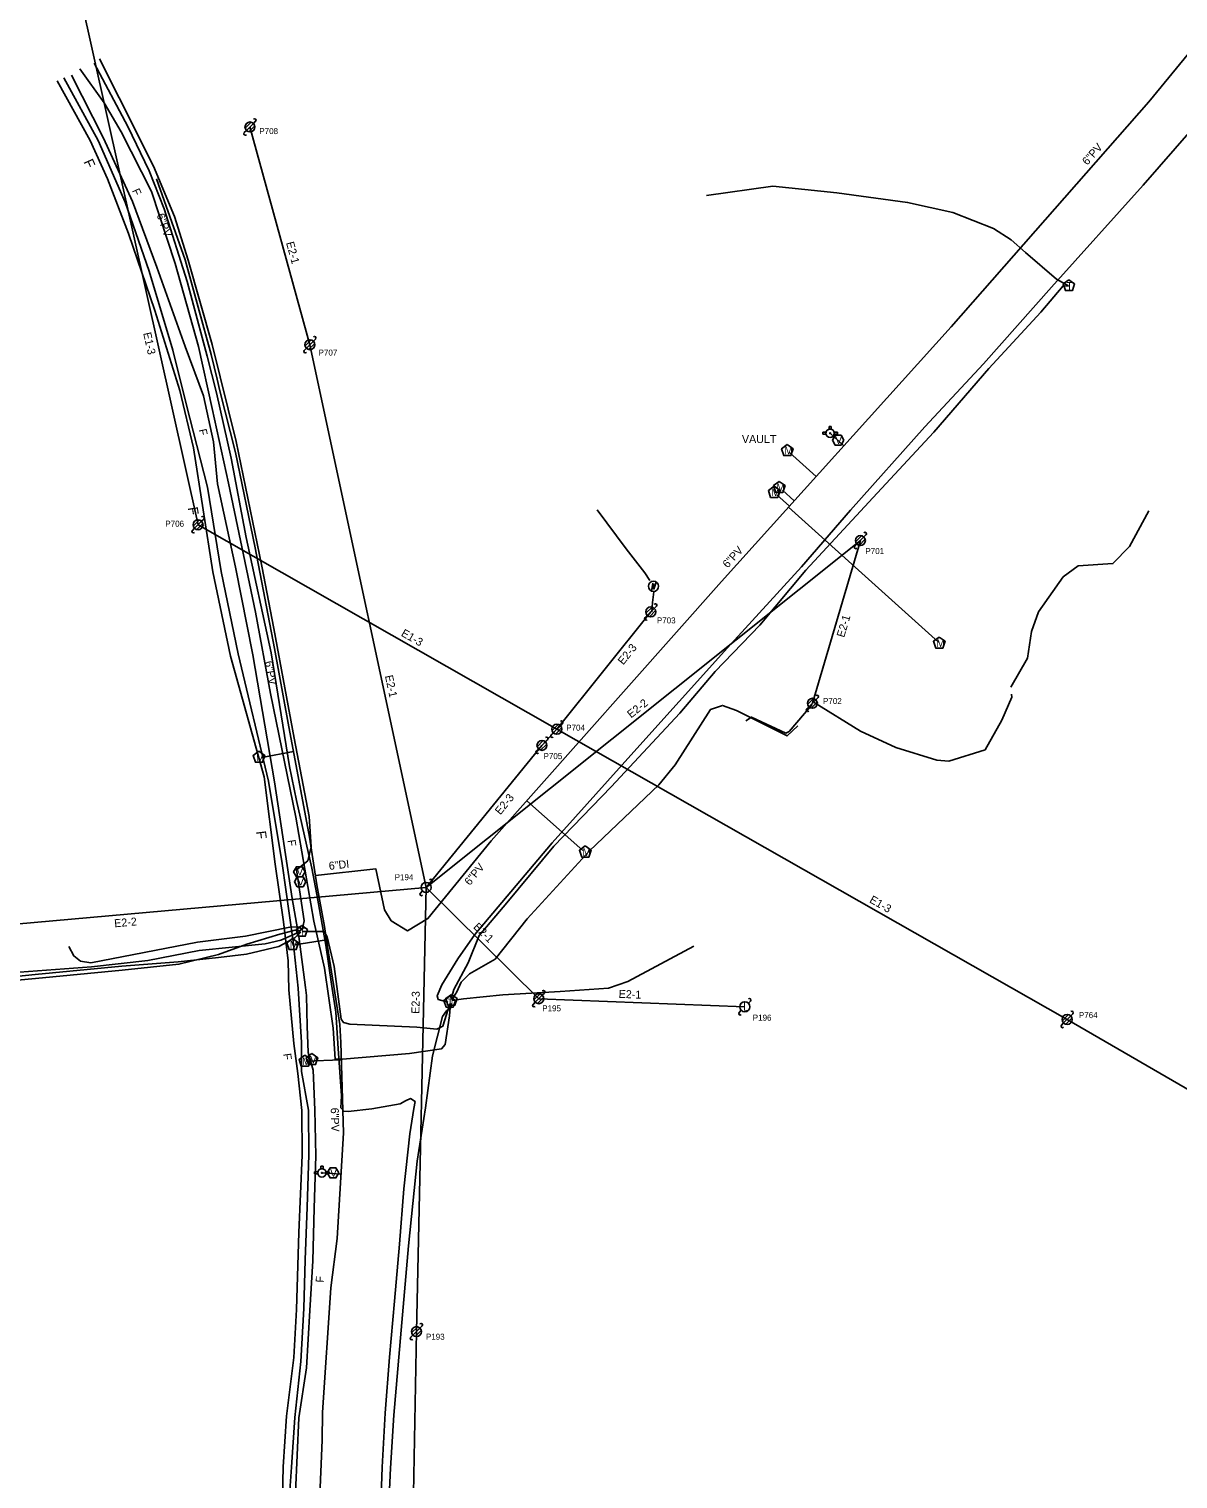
# Model space of a CAD drawing. Extents: x 1741604 to 1825760, y 1164229 to 1194908.
# Drawn here: x 1771883 to 1772457, y 1180447 to 1181171 of the extents above; entities that cross this region are included whole.
import ezdxf

# ---------------------------------------------------------------- set-up
doc = ezdxf.new("R2010")
doc.units = 0
for name, color, linetype in [('RD_EX_SU_Elec', 7, 'Continuous'), ('RD_EX_SU_H2O', 7, 'Continuous'), ('RD_EX_SU_Ovhd', 7, 'Continuous'), ('RD_EX_SU_Pole', 7, 'Continuous'), ('RD_EX_SU_Telecom', 7, 'Continuous'), ('RD_EX_SU_TX_H2O', 7, 'Continuous'), ('RD_EX_SU_TX_Pole', 7, 'Continuous'), ('RD_EX_SU_TX_Telecom', 7, 'Continuous')]:
    doc.layers.add(name, color=color, linetype=linetype)

# ---------------------------------------------------------------- blocks, each defined once
blk = doc.blocks.new('SUE_TPP')
at = {"layer": 'RD_EX_SU_Telecom'}
blk.add_lwpolyline([(0, 3), (-2.85, 0.93), (-1.76, -2.43), (1.76, -2.43), (2.85, 0.93)], close=True, dxfattribs=at)
blk.add_text('T', height=3.75, dxfattribs=at).set_placement((-1.25, -1.88))
blk = doc.blocks.new('SUE_PP')
at = {"layer": 'RD_EX_SU_Pole'}
for p, q in [((-2.41, -0.65), (0.65, 2.41)), ((-1.77, -1.77), (1.77, 1.77)), ((-0.65, -2.41), (2.41, 0.65)), ((1.77, 1.77), (2.83, 2.83)), ((-2.83, -2.83), (-1.77, -1.77))]:
    blk.add_line(p, q, dxfattribs=at)
blk.add_circle((0, 0), 2.5, dxfattribs=at)
for centre, start, end in [((2.3, 3.36), 315, 135), ((-2.3, -3.36), 135, 315)]:
    blk.add_arc(centre, 0.75, start, end, dxfattribs=at)
blk = doc.blocks.new('SUE_WV')
at = {"layer": 'RD_EX_SU_H2O'}
blk.add_lwpolyline([(2.89, 0), (1.44, 2.5), (-1.44, 2.5), (-2.89, 0), (-1.44, -2.5), (1.44, -2.5)], close=True, dxfattribs=at)
blk.add_text('V', height=3.75, dxfattribs=at).set_placement((-1.43, -1.88))
blk = doc.blocks.new('SUE_WFH')
at = {"layer": 'RD_EX_SU_H2O'}
for p, q in [((-2.01, 0.6), (-3.65, 0.6)), ((-3.65, 0.6), (-3.65, -0.45)), ((-0.48, 3.38), (-0.48, 2.04)), ((0.57, 3.38), (-0.48, 3.38)), ((0.57, 2.02), (0.57, 3.38)), ((3.7, 0.6), (2.01, 0.6)), ((3.7, -0.45), (3.7, 0.6)), ((-3.65, -0.45), (-2.05, -0.45)), ((2.05, -0.45), (3.7, -0.45))]:
    blk.add_line(p, q, dxfattribs=at)
for radius in [2.1, 0.263]:
    blk.add_circle((0, 0), radius, dxfattribs=at)
for start, end in [(163.3387, 192.31502), (74.24552, 103.21276), (347.68498, 16.6613)]:
    blk.add_arc((0, 0), 2.1, start, end, dxfattribs=at)
blk = doc.blocks.new('SUE_WM')
at = {"layer": 'RD_EX_SU_H2O'}
blk.add_lwpolyline([(0, 3.05), (-2.9, 0.94), (-1.79, -2.47), (1.79, -2.47), (2.9, 0.94)], close=True, dxfattribs=at)
blk.add_text('M', height=3.75, dxfattribs=at).set_placement((-1.43, -1.88))
blk = doc.blocks.new('SUE_ETM')
at = {"layer": 'RD_EX_SU_Elec'}
blk.add_lwpolyline([(1.24, 2.04), (0.23, -1.41), (-0.27, 0.46), (-1.03, -2.36), (-0.34, 1.55), (0.22, -0.39)], close=True, dxfattribs=at)
blk.add_circle((0, 0), 2.55, dxfattribs=at)

msp = doc.modelspace()

# ---------------------------------------------------------------- linework, layer by layer
at = {"layer": 'RD_EX_SU_Elec'}
for points in [[(1772166.5, 1180930.99), (1772181.07, 1180911.44), (1772190.3, 1180899.42), (1772192.86, 1180895.64)], [(1772193.85, 1180879.93), (1772194.2, 1180884.58), (1772194.89, 1180889.99)], [(1772240.86, 1180825.55), (1772243.66, 1180827.4), (1772260.87, 1180819.27), (1772262.4, 1180820.19), (1772274.05, 1180833.69)], [(1772274.93, 1180834.64), (1772298.08, 1180820.4), (1772315.7, 1180812.13), (1772336.3, 1180805.79), (1772342.21, 1180805.29), (1772360.4, 1180810.98), (1772368.82, 1180825.83), (1772373.82, 1180837.4), (1772373.57, 1180838.8)]]:
    msp.add_lwpolyline(points, dxfattribs=at)
at = {"layer": 'RD_EX_SU_H2O'}
for p, q in [((1772282.91, 1180969.23), (1772289.82, 1180963)), ((1772262.58, 1180959.61), (1772275.92, 1180947.58)), ((1772256.33, 1180938.42), (1772262.58, 1180932.79)), ((1772259.12, 1180940.78), (1772265, 1180935.47)), ((1772262.17, 1180932.33), (1772337.07, 1180864.8)), ((1771998.95, 1180807.18), (1772014.71, 1180810.13)), ((1772131.37, 1180785.58), (1772159.36, 1180760.73)), ((1772015.43, 1180713.54), (1772031.29, 1180716.02)), ((1772021.04, 1180655.5), (1772038.62, 1180656.05)), ((1772028.96, 1180599.58), (1772038.56, 1180599.02))]:
    msp.add_line(p, q, dxfattribs=at)
for points in [[(1772113.57, 1180765.54), (1772228.62, 1180895.12), (1772343.42, 1181022.45), (1772442.26, 1181134.91), (1772535.84, 1181249.02), (1772563.53, 1181288.52), (1772591.62, 1181328.82), (1772640.34, 1181415.41), (1772682.27, 1181505.27), (1772700.74, 1181551.33), (1772738.36, 1181647.58), (1772786.7, 1181777.24)], [(1771946.33, 1181096.31), (1771960.64, 1181055.82), (1771973.6, 1181008.54), (1771976.62, 1180996.3), (1771978.04, 1180990.49), (1771985.75, 1180959.54), (1771995.65, 1180911.92), (1772005.3, 1180861.73), (1772012.04, 1180824.37), (1772022.72, 1180767.33), (1772026.42, 1180743.62), (1772030.32, 1180722.72), (1772031.31, 1180715.87), (1772037.92, 1180673.78), (1772038.35, 1180664.76), (1772039.77, 1180619.55), (1772036.68, 1180566.85), (1772033.48, 1180542.16), (1772029.35, 1180479.91), (1772029.16, 1180466.1), (1772027.05, 1180418.5)], [(1772025.71, 1180748.18), (1772055.84, 1180751.59), (1772060.2, 1180731.07), (1772063.62, 1180725.56), (1772071.79, 1180720.62), (1772081.93, 1180726.7), (1772113.57, 1180765.54)]]:
    msp.add_lwpolyline(points, dxfattribs=at)
at = {"layer": 'RD_EX_SU_Ovhd'}
for p, q in [((1771888.17, 1181278.32), (1771967.08, 1180923.48)), ((1771993.03, 1181122.27), (1772022.97, 1181013.47)), ((1772022.97, 1181013.47), (1772081.03, 1180742.23)), ((1771967.08, 1180923.48), (1772146.37, 1180821.31)), ((1772081.03, 1180742.23), (1772298.04, 1180915.6)), ((1772274.06, 1180834.26), (1772298.04, 1180915.6)), ((1772146.37, 1180821.31), (1772193.3, 1180879.94)), ((1772138.94, 1180813.23), (1772146.37, 1180821.31)), ((1772146.37, 1180821.31), (1772401.4, 1180676.27)), ((1772081.03, 1180742.23), (1772138.94, 1180813.23)), ((1771857.86, 1180722.29), (1772081.03, 1180742.23)), ((1772076.21, 1180520.25), (1772081.03, 1180742.23)), ((1772081.03, 1180742.23), (1772137.34, 1180686.65)), ((1772137.34, 1180686.65), (1772240.32, 1180682.6)), ((1772401.4, 1180676.27), (1772645.63, 1180534.74)), ((1772072.6, 1180312.82), (1772076.21, 1180520.25))]:
    msp.add_line(p, q, dxfattribs=at)
at = {"layer": 'RD_EX_SU_Pole'}
for p, q in [((1772078.2, 1180739.4), (1772079.26, 1180740.47)), ((1772082.8, 1180744), (1772083.86, 1180745.06)), ((1772242.09, 1180684.37), (1772243.15, 1180685.43)), ((1772237.49, 1180679.77), (1772238.55, 1180680.83))]:
    msp.add_line(p, q, dxfattribs=at)
for centre in [(1772081.03, 1180742.23), (1772240.32, 1180682.6)]:
    msp.add_circle(centre, 2.5, dxfattribs=at)
for centre, start, end in [((1772083.33, 1180745.59), 315, 135), ((1772078.73, 1180738.87), 135, 315), ((1772242.62, 1180685.96), 315, 135), ((1772238.02, 1180679.24), 135, 315)]:
    msp.add_arc(centre, 0.75, start, end, dxfattribs=at)
at = {"layer": 'RD_EX_SU_Telecom'}
for points in [[(1772091.89, 1180684.87), (1772087.11, 1180686.29), (1772086.52, 1180688.08), (1772088.93, 1180693.62), (1772096.91, 1180706.61), (1772105.42, 1180718.77), (1772144.04, 1180764.5), (1772183.39, 1180808.36), (1772231.73, 1180862.02), (1772268.62, 1180902.51), (1772293.18, 1180930.86), (1772330.2, 1180972.4), (1772359.62, 1181003.89), (1772393.58, 1181042.3), (1772439.39, 1181093.24), (1772480.57, 1181140.31), (1772507.32, 1181173.35), (1772546.01, 1181222.2), (1772609.98, 1181309.67), (1772659.45, 1181393.41), (1772700.65, 1181486.4), (1772715.32, 1181519.93), (1772719.6, 1181522.19), (1772730.27, 1181518.08)], [(1771915.16, 1181154.11), (1771931.91, 1181122.48), (1771942.63, 1181100.42), (1771950.22, 1181081.36), (1771961.67, 1181045.09), (1771971.58, 1181007.75), (1771976.25, 1180989.42), (1771983.6, 1180956.79), (1771991.09, 1180917.05), (1772003.57, 1180859.55), (1772012.74, 1180802.76), (1772016.33, 1180785.64), (1772023.87, 1180751.91), (1772026.38, 1180738.65), (1772030.93, 1180713.46), (1772033.7, 1180693.82)], [(1771917.79, 1181156.28), (1771927.62, 1181136.81), (1771944.74, 1181102.65), (1771955.34, 1181077.57), (1771962.2, 1181055.67), (1771974.12, 1181013.54), (1771986.2, 1180965.12), (1771998.99, 1180902.73), (1772005.01, 1180871.62), (1772015.11, 1180816.88), (1772022.57, 1180777.7), (1772023.66, 1180762.52), (1772022.01, 1180755.61), (1772016.23, 1180751.12), (1772020.05, 1180725.5), (1772019.08, 1180720.83)], [(1771896.64, 1181145.31), (1771913.21, 1181115.46), (1771921.78, 1181096.31), (1771932.3, 1181069.05), (1771945.56, 1181030.61), (1771958.05, 1180990.5), (1771964.87, 1180962.01), (1771974.5, 1180899.94), (1771983.32, 1180857.86), (1772000.11, 1180797.46), (1772005.64, 1180753.88), (1772009.8, 1180725.1), (1772012.18, 1180705.59), (1772012.4, 1180691.05)], [(1771900.06, 1181146.75), (1771917.14, 1181115.59), (1771930.6, 1181084.73), (1771942.57, 1181050.14), (1771954.42, 1181010.69), (1771961.18, 1180983.97), (1771971.88, 1180942.27), (1771978.71, 1180900.18), (1771987.08, 1180858.9), (1772002.34, 1180795.39), (1772009.12, 1180754.22), (1772014.54, 1180715.3), (1772017.04, 1180691.88)], [(1771903.86, 1181148.19), (1771919.84, 1181116.73), (1771934.24, 1181085.07), (1771946.42, 1181052.14), (1771960.63, 1181012.55), (1771969.87, 1180987.89), (1771974.81, 1180964.86), (1771976.79, 1180943.99), (1771985.8, 1180902.22), (1771994.39, 1180858.54), (1772005.26, 1180794.94), (1772014.19, 1180736.79), (1772017.43, 1180717.74), (1772020.81, 1180692.29)], [(1771908.05, 1181151.32), (1771920.11, 1181134.3), (1771928.6, 1181119.86), (1771943.75, 1181089.97), (1771955.68, 1181054.1), (1771967.37, 1181012.61), (1771974.13, 1180981.54), (1771982.29, 1180944.2), (1771995.79, 1180879.74), (1772003.33, 1180839.12), (1772015.99, 1180777.28), (1772024.89, 1180725.41), (1772030.2, 1180701.82), (1772034.65, 1180671.88), (1772035.58, 1180656.39), (1772039.28, 1180656.4), (1772072.7, 1180659.3), (1772088.74, 1180661.63), (1772090.58, 1180663.74), (1772092.74, 1180678.15), (1772093.18, 1180684.24)], [(1772221.21, 1181088), (1772254.32, 1181092.62), (1772286.36, 1181089.39), (1772321.68, 1181084.55), (1772344.19, 1181079.54), (1772364.57, 1181071.5), (1772373.36, 1181065.87), (1772380.63, 1181059.54), (1772396.07, 1181046.28), (1772402, 1181042.87)], [(1772093.53, 1180686.4), (1772094.89, 1180691.23), (1772102.07, 1180704.55), (1772107.6, 1180718.14), (1772121.36, 1180734.51), (1772144.84, 1180762.93), (1772173.47, 1180792.57), (1772207.87, 1180829.31), (1772225.42, 1180850.1), (1772247.74, 1180873.29), (1772270.81, 1180900.83), (1772308.54, 1180941.66), (1772334.71, 1180969.75), (1772362.3, 1181001.58), (1772388.25, 1181029.81), (1772399.37, 1181042.95), (1772402.07, 1181042.65)], [(1772373.31, 1180842.38), (1772381.59, 1180856.87), (1772383.57, 1180870.15), (1772387.14, 1180880.03), (1772399.39, 1180897.42), (1772406.97, 1180902.93), (1772424.29, 1180904.12), (1772432.57, 1180912.64), (1772442.18, 1180930.39)], [(1772205.44, 1180803.45), (1772223.14, 1180831.08), (1772229.1, 1180833.17), (1772236.2, 1180830.61)], [(1772236.2, 1180830.61), (1772261.47, 1180817.97), (1772266.82, 1180823)], [(1772093.86, 1180686.12), (1772096.37, 1180690.13), (1772098.61, 1180694.9), (1772102.73, 1180698.99), (1772115.54, 1180706.34), (1772131.63, 1180726.5), (1772162.62, 1180760.61), (1772197.35, 1180793.53), (1772205.44, 1180803.45)], [(1771587.15, 1180459.73), (1771589.21, 1180479.94), (1771594.54, 1180498.57), (1771604.64, 1180518.89), (1771620.34, 1180538.47), (1771644.7, 1180562.03), (1771656.29, 1180575.92), (1771676.28, 1180601.07), (1771696.75, 1180642.18), (1771715.12, 1180663.08), (1771734.81, 1180675.7), (1771753.58, 1180681.9), (1771803.62, 1180689.32), (1771855.23, 1180693.88), (1771885.92, 1180696.78), (1771929.22, 1180700.82), (1771957.5, 1180703.88), (1771977.31, 1180708.74), (1771991.43, 1180713.91), (1772007.96, 1180718.9), (1772016.21, 1180721.06), (1772018.22, 1180720.58)], [(1771673.08, 1180710.15), (1771725.33, 1180692.64), (1771754.29, 1180689.69), (1771834.8, 1180695.43), (1771868.85, 1180699.19), (1771913.8, 1180702.63), (1771941.97, 1180705.7), (1771967.65, 1180710.79), (1772000.6, 1180714.01), (1772008.52, 1180715.93), (1772018.24, 1180720.18)], [(1771753.67, 1180682.97), (1771803.71, 1180690.91), (1771855, 1180695.57), (1771885.61, 1180698.79), (1771929.06, 1180702.84), (1771957.15, 1180705.08), (1771977.25, 1180707.15), (1771991.28, 1180708.86), (1772007.5, 1180712.7), (1772015.5, 1180717.03), (1772018.36, 1180719.84)], [(1771902.53, 1180712.76), (1771905.04, 1180708.04), (1771908.37, 1180705.41), (1771913.45, 1180704.61), (1771966.87, 1180714.89), (1771990.79, 1180717.81), (1772013.01, 1180722.35), (1772017.99, 1180722.57), (1772018.74, 1180720.65)], [(1772019.19, 1180720.22), (1772030.14, 1180720.2), (1772031.68, 1180717.6), (1772035.13, 1180702.65), (1772038.63, 1180676.45), (1772039.76, 1180674.77), (1772042.85, 1180673.95), (1772076.4, 1180672.36), (1772086.4, 1180671.38), (1772089.48, 1180672.86), (1772092.89, 1180684.05)], [(1772093.9, 1180685.69), (1772099.69, 1180686.56), (1772119.43, 1180688.61), (1772147.97, 1180690.23), (1772172.18, 1180691.83), (1772181.77, 1180695.17), (1772214.8, 1180712.82)], [(1772012.4, 1180691.05), (1772014.96, 1180664.17), (1772016.98, 1180649.27), (1772018.9, 1180630.77), (1772019.09, 1180608.47), (1772017.52, 1180569.82), (1772016.3, 1180531.32), (1772014.96, 1180507.29), (1772011.23, 1180478.08), (1772009.64, 1180452.63), (1772008.51, 1180400.68), (1772008.17, 1180360.43), (1772009.54, 1180320.86), (1772012.41, 1180281.05), (1772014.97, 1180244.87), (1772018.85, 1180205.33), (1772021.16, 1180180.29), (1772026.12, 1180158.87), (1772029.53, 1180133.75), (1772032.05, 1180118.67), (1772034.35, 1180108.62), (1772035.86, 1180102.65)], [(1772017.04, 1180691.88), (1772018.72, 1180664.67), (1772018.85, 1180650.21), (1772022.23, 1180630.88), (1772022.45, 1180608.65), (1772021.66, 1180582.51), (1772020.66, 1180556.08), (1772020, 1180531.89), (1772018.46, 1180505.27), (1772015.48, 1180477.33), (1772013.83, 1180452.5), (1772011.97, 1180426.89)], [(1772020.81, 1180692.29), (1772021.27, 1180688.23), (1772021.68, 1180672.96), (1772022.14, 1180659.78), (1772024.54, 1180651), (1772025.43, 1180631.15), (1772025.9, 1180608.06), (1772025.16, 1180581.97), (1772024.46, 1180555.62), (1772022.98, 1180530.76), (1772021.28, 1180502.21), (1772017.52, 1180477.19), (1772015.73, 1180439.92), (1772014.84, 1180427.29), (1772013.76, 1180386.43), (1772012.51, 1180360.39), (1772013.33, 1180334.64), (1772013.48, 1180321.01), (1772015.66, 1180295.14), (1772017.49, 1180268.59), (1772019.54, 1180245.54), (1772022.98, 1180205.51), (1772023.89, 1180198.24), (1772026.76, 1180190.86)], [(1772033.7, 1180693.82), (1772035.89, 1180679.86), (1772037.12, 1180661.79), (1772038.81, 1180638.02), (1772038.35, 1180632.14), (1772039.93, 1180630.4), (1772042.16, 1180630.28), (1772053.92, 1180631.61), (1772068.02, 1180634.1), (1772070.78, 1180635.65), (1772073.19, 1180636.71), (1772075.59, 1180635.24), (1772074.94, 1180631.81), (1772072.94, 1180619.04), (1772069.95, 1180591.63), (1772067.71, 1180563.97), (1772065.31, 1180535.43), (1772062.67, 1180507.57), (1772060.59, 1180479.54), (1772059.04, 1180452.51), (1772058.05, 1180424.17)], [(1772093.26, 1180684.17), (1772093.78, 1180683.39), (1772093.38, 1180682.04), (1772091.18, 1180680.53), (1772089.29, 1180677.82), (1772084.23, 1180658.05), (1772080.74, 1180632.02), (1772076.55, 1180605.53), (1772072.26, 1180563.1), (1772068.53, 1180520.99), (1772064.99, 1180478.55), (1772063.24, 1180452.07), (1772061.27, 1180409.29), (1772060.04, 1180368.49), (1772059.73, 1180343.81), (1772059.04, 1180317.82), (1772061.04, 1180294.69), (1772063.08, 1180269.32), (1772066.45, 1180228.96), (1772069.24, 1180201.17), (1772075.4, 1180171.53)]]:
    msp.add_lwpolyline(points, dxfattribs=at)

# ---------------------------------------------------------------- block references
at = {"layer": 'RD_EX_SU_Elec'}
msp.add_blockref('SUE_ETM', (1772194.69, 1180892.73), dxfattribs=at)
at = {"layer": 'RD_EX_SU_H2O'}
for name, p in [('SUE_WFH', (1772282.91, 1180969.23)), ('SUE_WM', (1772261.55, 1180960.56)), ('SUE_WV', (1772286.95, 1180965.74)), ('SUE_WM', (1772255, 1180939.66)), ('SUE_WM', (1772257.55, 1180942.1)), ('SUE_WM', (1772337.48, 1180864.31)), ('SUE_WM', (1771997.51, 1180807.27)), ('SUE_WM', (1772160.59, 1180759.9)), ('SUE_WV', (1772017.69, 1180750.1)), ('SUE_WV', (1772018.11, 1180745.12)), ('SUE_WM', (1772014.35, 1180713.63)), ('SUE_WM', (1772024.02, 1180656.16)), ('SUE_WM', (1772020.47, 1180655.38)), ('SUE_WFH', (1772028.96, 1180599.58)), ('SUE_WV', (1772034.54, 1180599.56))]:
    msp.add_blockref(name, p, dxfattribs=at)
at = {"layer": 'RD_EX_SU_Pole'}
for p in [(1771993.03, 1181122.27), (1772022.97, 1181013.47), (1771967.08, 1180923.48), (1772298.04, 1180915.6), (1772193.3, 1180879.94), (1772274.06, 1180834.26), (1772146.37, 1180821.31), (1772138.94, 1180813.23), (1772137.34, 1180686.65), (1772401.4, 1180676.27), (1772076.21, 1180520.25)]:
    msp.add_blockref('SUE_PP', p, dxfattribs=at)
at = {"layer": 'RD_EX_SU_Telecom'}
for p in [(1772402.28, 1181042.91), (1772018.91, 1180720.25), (1772093.71, 1180685.81), (1772092.81, 1180684.85)]:
    msp.add_blockref('SUE_TPP', p, dxfattribs=at)

# ---------------------------------------------------------------- texts
at = {"layer": 'RD_EX_SU_Ovhd'}
for s, rotation, p in [('E2-1', 285.3879, (1772011.03, 1181064.39)), ('E1-3', 282.53643, (1771939.64, 1181019.21)), ('E2-1', 73.57466, (1772289.94, 1180866.9)), ('E1-3', 330.32481, (1772068.21, 1180868.16)), ('E2-3', 51.3239, (1772179.57, 1180853.18)), ('E2-1', 282.0816, (1772060.45, 1180847.93)), ('E2-2', 38.62203, (1772183.48, 1180826.64)), ('E2-3', 50.79608, (1772118.14, 1180778.23)), ('E1-3', 330.37183, (1772302.25, 1180734.96)), ('E2-2', 5.10586, (1771925.37, 1180722.3)), ('E2-1', 315.37285, (1772104.38, 1180722.19)), ('E2-3', 88.75443, (1772077.66, 1180679.07)), ('E2-1', 357.74565, (1772177.21, 1180687.09))]:
    msp.add_text(s, height=4, rotation=rotation, dxfattribs=at).set_placement(p)
at = {"layer": 'RD_EX_SU_Pole'}
for p in [(1772080.17, 1180740.23), (1772239.46, 1180680.6)]:
    msp.add_text('L', height=4, dxfattribs=at).set_placement(p)
at = {"layer": 'RD_EX_SU_TX_H2O'}
for s, rotation, p in [('6"PV', 48.68816, (1772411.46, 1181102.9)), ('6"PV', 289.46453, (1771946.33, 1181078.3)), ('6"PV', 47.96221, (1772231.74, 1180901.57)), ('6"PV', 280.22723, (1772000.42, 1180855.02)), ('6"DI', 6.44276, (1772032.64, 1180750.98)), ('6"PV', 50.82834, (1772102.9, 1180742.94)), ('6"PV', 271.79264, (1772033.37, 1180632.1))]:
    msp.add_text(s, height=4, rotation=rotation, dxfattribs=at).set_placement(p)
msp.add_text('VAULT', height=4, dxfattribs=at).set_placement((1772238.87, 1180964.33))
at = {"layer": 'RD_EX_SU_TX_Pole'}
for s, p in [('P708', (1771997.69, 1181118.72)), ('P707', (1772027.32, 1181008.04)), ('P706', (1771950.72, 1180922.52)), ('P701', (1772300.56, 1180908.84)), ('P703', (1772196.37, 1180874.18)), ('P702', (1772279.38, 1180833.88)), ('P704', (1772151.06, 1180820.59)), ('P705', (1772139.74, 1180806.37)), ('P194', (1772065.32, 1180745.87)), ('P195', (1772139.07, 1180680.33)), ('P196', (1772244.28, 1180675.66)), ('P764', (1772407.26, 1180676.93)), ('P193', (1772080.95, 1180516.23))]:
    msp.add_text(s, height=3, dxfattribs=at).set_placement(p)
at = {"layer": 'RD_EX_SU_TX_Telecom'}
for height, rotation, p in [(5, 294.11623, (1771909.72, 1181104.89)), (4, 294.45477, (1771933.98, 1181090.46)), (4, 282.09454, (1771967.36, 1180970.97)), (5, 278.81471, (1771961.93, 1180932.02)), (5, 277.23812, (1771996.01, 1180770.2)), (4, 278.72776, (1772011.76, 1180765.78)), (4, 277.70308, (1772009.6, 1180659.08)), (4, 86.59267, (1772029.82, 1180544.69))]:
    msp.add_text('F', height=height, rotation=rotation, dxfattribs=at).set_placement(p)

doc.saveas('drawing.dxf')
